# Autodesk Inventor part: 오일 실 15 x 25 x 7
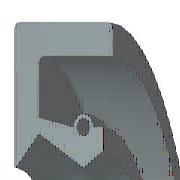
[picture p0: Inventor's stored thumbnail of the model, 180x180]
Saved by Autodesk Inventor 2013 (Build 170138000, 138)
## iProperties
Created: 2012-02
Part Number: 오일 실 15 x 25 x 7
Material: 고무
Description: 오일-실
Document SubType Name: Modeling
Standard: KS B 2804
Designer: mduedu
Standards Organization: KS
Language: ko-KR
Size Designation: D - 15 25 7
Categories: <MemberInstance><Categories><Category DisplayName="샤프트 부품" InternalName="7f7aeb1f-a693-4053-b835-cee3144e0d98" Mnemonic="SHFT"><Category DisplayName="실링" Intern
Density: 0.93 g/cm^3
Mass: 1.46464 g
Surface Area: 21.6685 cm^2
Volume: 1.57488 cm^3
IsCustomPart: 1
Author: mduedu
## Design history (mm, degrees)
revolve "본체" stored, may be unused: angle "d17" = 90 deg
revolve "스프링1" stored, may be unused: angle "d18" = 90 deg
body "Solid1"
sketch "스케치1"
  geometry: L1 (0, 12.5)-(7, 12.5); L2 (7, 10.75)-(1.75, 10.75); L3 (1.75, 9.25)-(4.9, 7.5); L4 (4.9, 7.5)-(0, 7.5); L5 (0, 0)-(9.586, 0) reference; L6 (4.9, 7.5)-(6.3, 8.375); L7 (0, 18)-(0, -3) reference; L8 (-1.941, 0)-(11.507, 0) reference; L9 (4.2, 9.6)-(1.75, 10.09); L10 (1.75, 10.09)-(1.75, 10.75); L11 (0, 12.5)-(0, 7.588); L12 (4.9, 7.5)-(0, 7.5); L13 (1.75, 9.25)-(0.152, 7.528); L14 (7, 12.5)-(7, 10.75); L15 (5.6, 9.6)-(6.3, 9.6); L16 (6.3, 9.6)-(6.3, 8.375); C1 r 0.455 at (4.9, 9.6); A1 r 0.7 centre (4.9, 9.6) between (5.6, 9.6) and (4.2, 9.6); A2 r 0.088 centre (0.088, 7.588) between (0, 7.588) and (0.152, 7.528); 1 further point
  constraints: 28 end point, 5 horizontal alignment, 5 point on line, 4 point on circle, 4 vertical alignment, 3 centre point, 3 tangent, 2 collinear, 2 horizontal, 2 perpendicular, 1 coincident, 1 parallel
  dimensions: "d0" = 25 diameter of L1 L5 (= SD2); "d1" = 1.75 distance of L1.end L2.start (= SD); "d2" = 0.91 diameter of C1 (= SPDI); "d3" = 1.4 diameter of A1 (= SPDA); "d4" = 15 diameter of L3.end L5 (= NND); "d5" = 18.5 diameter of L3.start L5 (= TKDM); "d7" = 20.18 diameter of L9.end L5 (= TKDM + 0.24 x SWDT); "d8" = 1.75 distance between parallel lines of L11 L10 (= SD); "d9" = 4.9 distance from line of L11 C1.centre (= SPDST); "d10" = 19.2 diameter of C1.centre L5 (= HLDM); "d11" = 0.0875 radius of A2 (= 0.25 x LAB); "d12" = 6.3 distance between parallel lines of L11 L16 (= SDI); "d13" = 16.75 diameter of L6.end L5 (= ABDM); "d14" = 7 distance from line of L11 L1.end (= SWDT)
fillet "모깎기1" dims "d6" = 0.3 (= RR)
other parameters: "SD2" = 25 [user parameter; used in 1 equation term], "SWDT" = 7 [user parameter; used in 2 equation terms], "RR" = 0.3 [user parameter; used in 1 equation term], "SD" = 1.75 [user parameter; used in 2 equation terms], "NND" = 15 [user parameter; used in 1 equation term], "SPDA" = 1.4 [user parameter; used in 1 equation term], "SPDI" = 0.91 [user parameter; used in 1 equation term], "TKDM" = 18.5 [user parameter; used in 2 equation terms], "HLDM" = 19.2 [user parameter; used in 1 equation term], "ABDM" = 16.75 [user parameter; used in 1 equation term], "SDI" = 6.3 [user parameter; used in 1 equation term], "SPDST" = 4.9 [user parameter; used in 1 equation term], "LAB" = 0.35 [user parameter; used in 1 equation term], "d15" = 0, "d16" = 0, "d19" = 0
